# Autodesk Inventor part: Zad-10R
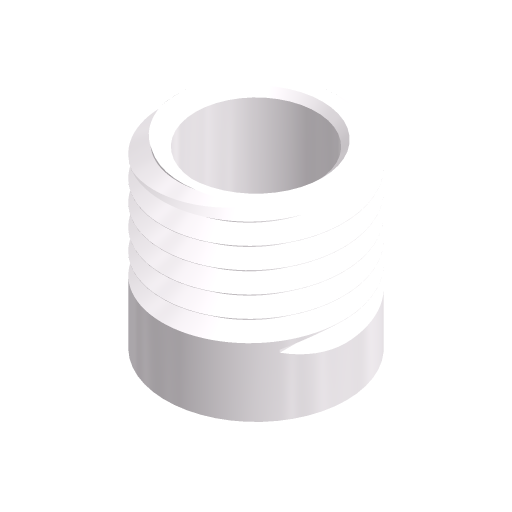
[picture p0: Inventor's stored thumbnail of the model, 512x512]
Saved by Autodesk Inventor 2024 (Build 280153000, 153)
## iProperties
Company: ATC
Shininess: 20.0
Length Units: 11269
Angle Units: 11279
Time Units: 11290
Mass Units: 11283
Length Display Precision: 3
Angle Display Precision: 2
Created: 2023-03
Part Number: Zad-10R
Document SubType Name: Modeling
Designer: Andrzej Jaskulski
Material: Kurs-AJ
Density: 1 g/cm^3
Appearance: Kurs-AJ
Checked By: A.J.
Engr Approved By: Andrzej Jaskulski
Mfg Approved By: Andrzej Jaskulski
Authority: A.J.
Density: 0.0
Volumn: 0.0
Area: 0.0
PropertySet Name: Model Information
Control State: 0
Master: False
Checked Out: False
Title: A.J.: Kurs R2024-MEP
Author: Andrzej Jaskulski
Revision Number: 1/24
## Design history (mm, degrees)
extrude "Korpus" new body distance "d2" = 30 (computed from dlugosc); taper "d3" = 0 deg
  node "Szkic 1" dims "d1" = 30 (= d)
node "OśKonstrukcyjna1"
node "PłaszczyznaKonstrukcyjna1"
node "PłaszczyznaKonstrukcyjna2"
node "Płaszczyzna konstrukcyjna3"
sketch "Szkic 2"
  geometry: C1 r 5 at (0, 0)
  constraints: 1 centre point
  dimensions: "d11" = 10 diameter of C1
extrude "Trzpień" join sketch "Szkic 2" distance "d12" = 5; taper "d13" = 0 deg
extrude "Otwór" cut distance "d14" = 25 (computed from dlugosc); taper "d15" = 0 deg
  node "Szkic 3"
chamfer "Faza pod gwint" distance "d16" = 1.89443 (= 0.625 x h); stored, may be unused: second distance "d17" = 1.89443 (= 0.625 x h), angle "d30" = 45 deg
chamfer "Inne fazy" distance "d18" = 1; stored, may be unused: second distance "d19" = 1, angle "d31" = 45 deg
sketch "Szkic 4"
  geometry: L1 (-15, 8.279)-(-12.398, 9.781); L2 (-12.398, 9.781)-(-12.398, 10.219); L3 (-12.398, 10.219)-(-15, 11.721); L4 (-15, 8.279)-(-15, 11.721)
  constraints: 8 end point, 2 vertical
extrude "Wyjście narzędzia" cut sketch "Szkic 4" distance "d20" = 15 (= 0.5 x d); taper "d21" = 0 deg
feature "Gwint" pitch "d22" = 3.5; turns "d24" = 7; dims "d23" = 10, "d25" = 0, angle "d26" = 90 deg, angle "d27" = 90 deg, "d28" = 0, "d29" = 0
node "Bryła1"
node "Korpusy bryłowe"
node "Korpusy powierzchniowe"
other parameters: "dejeden" = 26.211 [user parameter], "dedwa" = 27.727 [user parameter], "p" = 3.5 [user parameter; used in 1 equation term], "h" = 3.03109 (= 0.866025 x p) [user parameter; used in 2 equation terms], "d4" = 0, "d5" = 0, "d6" = 0, "d7" = 0, "d8" = 0
